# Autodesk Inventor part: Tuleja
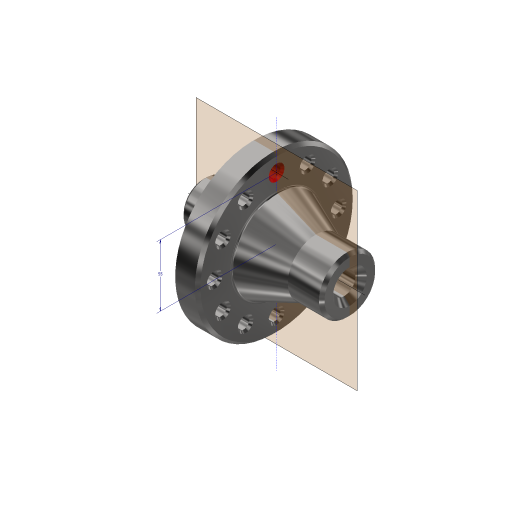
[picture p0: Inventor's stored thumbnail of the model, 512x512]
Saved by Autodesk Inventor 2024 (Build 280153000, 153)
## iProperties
Company: ATC
Shininess: 21.0
Length Units: 11269
Angle Units: 11279
Time Units: 11290
Mass Units: 11283
Length Display Precision: 3
Angle Display Precision: 2
Compacted: True
Created: 2023-03
Part Number: Tuleja
Document SubType Name: Modeling
Designer: Andrzej Jaskulski
Material: 18G2A
Description: wg ATC-08
Density: 7.85 g/cm^3
Appearance: Stal — polerowana
Checked By: A.J.
Engr Approved By: Andrzej Jaskulski
Mfg Approved By: Andrzej Jaskulski
Authority: A.J.
Density: 0.0
Volumn: 0.0
Area: 0.0
PropertySet Name: Model Information
Control State: 0
Master: False
Checked Out: False
Title: A.J.: Kurs R2024-MEP
Author: Andrzej Jaskulski
Revision Number: 1/24
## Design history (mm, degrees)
sketch "Zarys"
  geometry: L1 (0, 0)-(140, 0); L2 (0, 10)-(130, 10); L3 (130, 10)-(130, 25); L4 (130, 25)-(100, 25); L5 (100, 25)-(65, 39.857); L6 (65, 39.857)-(65, 70); L7 (65, 70)-(45, 70); L8 (45, 70)-(45, 20); L9 (45, 20)-(0, 20); L10 (0, 20)-(0, 10)
  constraints: 20 end point, 7 parallel, 1 horizontal, 1 perpendicular, 1 vertical alignment, 1 other
  dimensions: "d5" = 30 distance of L3.end L4.end; "d6" = 45 distance between parallel lines of L8 L10; "d7" = 65 distance between parallel lines of L6 L10; "d8" = 23 deg angle of L5 L4; "d35" = 20 diameter of L2 L1; "d36" = 40 diameter of L9 L1; "d37" = 140 diameter of L7 L1; "d38" = 50 diameter of L4 L1; "d39" = 130 distance of L2.start L2.end
revolve "BAZA" sketch "Zarys" stored, may be unused: angle "d9" = 90 deg
node "Płaszczyzna symetrii XZ"
  node "Oś"
sketch "Szkic Rowka"
  geometry: L1 (-115, 20)-(-70, 20) reference; L2 (-70, -70)-(-70, 70) reference; L3 (-141, 0)-(41, 0) reference; C1 r 5 at (-71.5, 21.5)
  constraints: 1 centre point
  dimensions: "d41" = 1.5 distance from line of C1.centre L1; "d42" = 1.5 distance from line of C1.centre L2; "d43" = 10 diameter of C1
revolve "Podcięcie" sketch "Szkic Rowka" stored, may be unused: angle "d15" = 90 deg
chamfer "Fazy zewnętrzne" distance "d16" = 2.5; stored, may be unused: second distance "d17" = 2.5, angle "d32" = 45 deg
chamfer "Fazy wewnętrzne" distance "d18" = 5; stored, may be unused: second distance "d19" = 5, angle "d33" = 45 deg
fillet "Zaokrąglenie" dims "d31" = 2
sketch "Położenie otworu"
  geometry: L1 (98, 0)-(-98, 0) reference; 2 further points
  constraints: 1 point on line
  dimensions: "d44" = 55 distance of point (-55, 0) point (0, 0)
hole "Otwór bazowy" sketch "Położenie otworu" at (-55, 0) diameter "d21" = 10.5; stored, may be unused: countersink angle "d25" = 90 deg, drill point angle "d27" = 118 deg; dims "d22" = 6, "d23" = 14, "d24" = 2, "d26" = 8
node "Oś otworu"
pattern_circular "Szyk otworów" dims angle "d30" = 360 deg
node "Bryła1"
node "Korpusy bryłowe"
node "Korpusy powierzchniowe"
node "Początek"
node "Płaszczyzna YZ"
node "Płaszczyzna XZ"
node "Płaszczyzna XY"
node "Oś X"
node "Oś Y"
node "Oś Z"
node "Punkt  środkowy"
other parameters: "d10" = 0, "d40" = 0
